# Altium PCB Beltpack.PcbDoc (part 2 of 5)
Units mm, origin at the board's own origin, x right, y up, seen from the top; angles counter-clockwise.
Board outline 85 x 81 mm, 4 copper layers (Top Layer, Inner-1, Inner_GND, Bottom Layer), stack 1.556 mm thick; 389 components, 291 nets, 1372 pads, 660 vias.
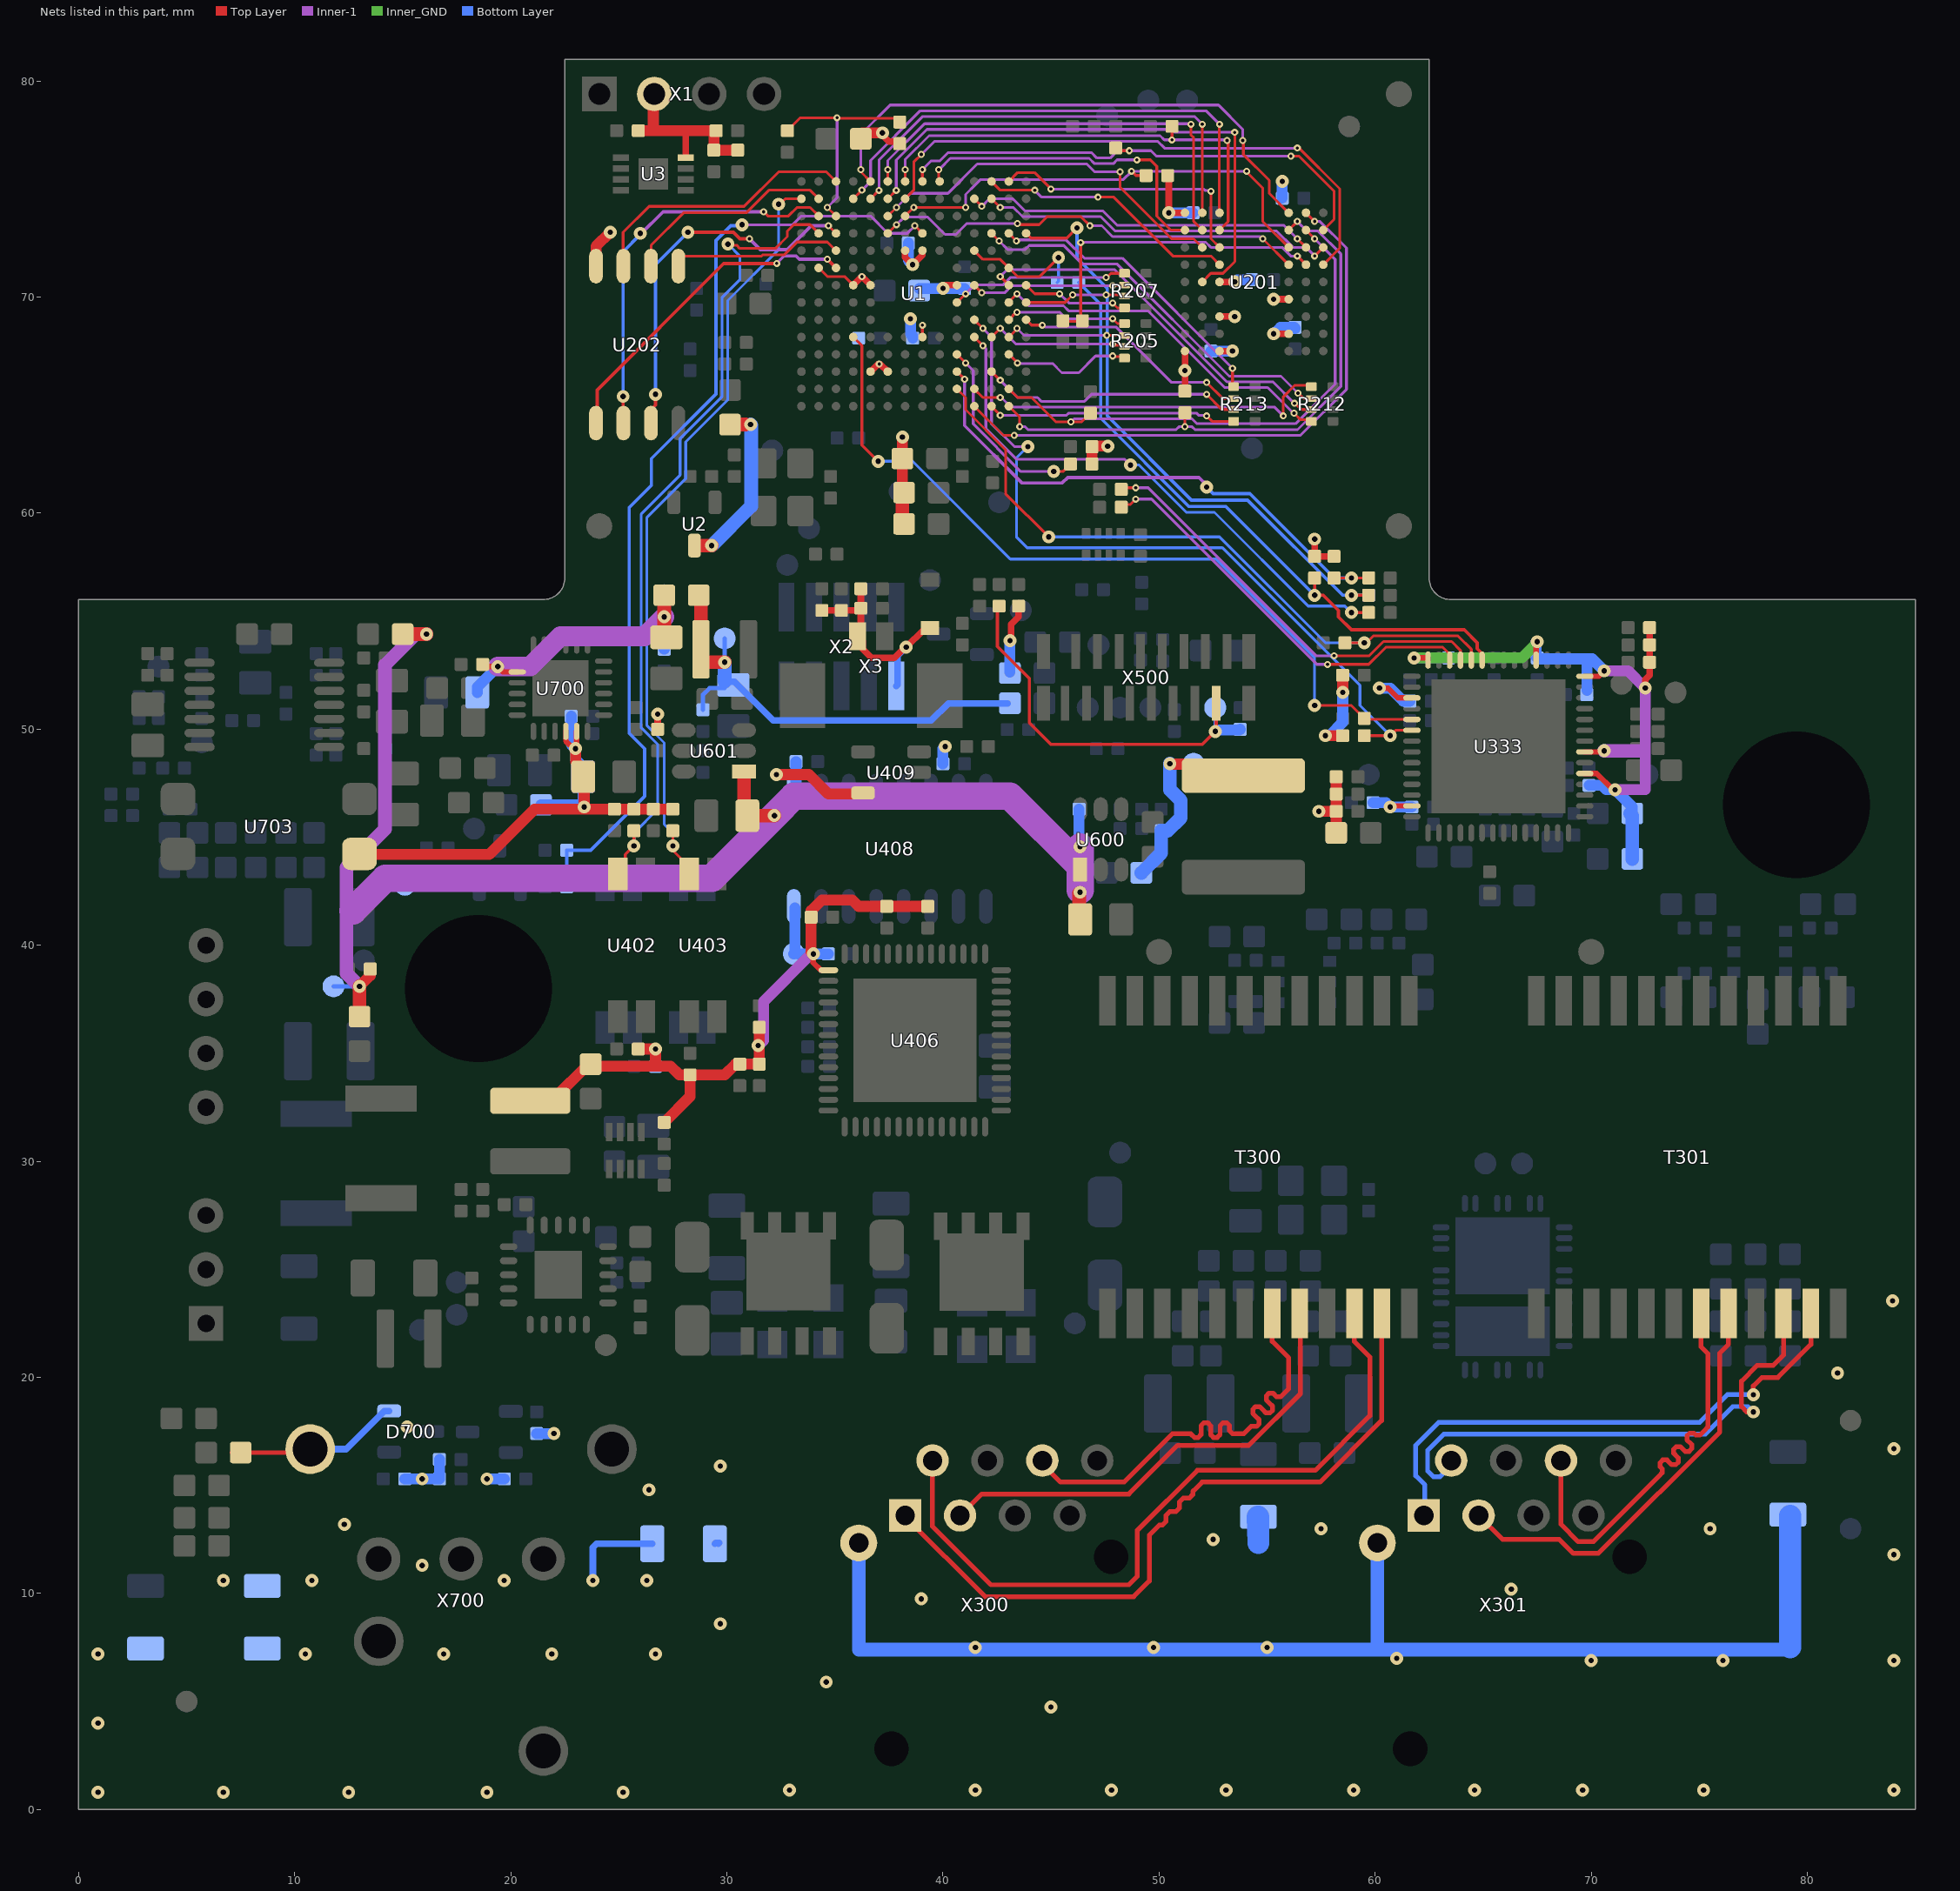
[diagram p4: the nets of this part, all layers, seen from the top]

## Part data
C1 C2: library part C.C0G0402TJ-15P0, "Capacitor C0G, 0402, 50V, 5%", Mfr Name=Murata, Mfr Part No=GRM1555C1H150JA01D
C3 C5 C19 C310 C713: library part C.C0G0402TJ-220P, "Capacitor C0G, 0402, 50V, 5%", Mfr Name=Murata, Mfr Part No=GRM1555C1H221JA01D, VOLTAGE=50V
C4 C7 C9 C10 C12 C15 C200 C201 C202 C203 C204 C205 C300 C301 C302 C303 C304 C305 C306 C308 C309 C313 C315 C316 C318 C412 C416 C417 C418 C605 C700 C702 C704 C706 C708 C711 C723 C725: library part C.X7R0402CM-100N, "Capacitor X7R, 0402, 16V, 20%", Mfr Name=Kemet, Mfr Part No=C0402C104M4RACAUTO, VOLTAGE=16V
C6 C8 C13: library part C.X7R0603TK-4N70, "Capacitor X7R, 0603, 50V, 10%", Mfr Name=Panasonic, Mfr Part No=ECJ1VB1H472K
C11 C16 C307 C311 C312 C317 C410 C600 C603 C710 C714 C715 C722: library part C.X7R0603EK-1U00, "Capacitor X7R, 0603, 25V, 10%", Mfr Name=Murata, Mfr Part No=GRM188R71E105KA12D, VOLTAGE=25V
C14 C411 C602: library part C.X5R0603JM-22U0, "Capacitor X5R, 0603, 6V3, 20%", Mfr Name="TDK Corporation", Mfr Part No=GRM188R60J226MEA0J, VOLTAGE=6.3V
C17 C18: library part C.X7R0603EK-1U00, "Capacitor X7R, 0603, 25V, 10%", Mfr Name=Samsung, Mfr Part No=CL10B105KA8NFNC, VOLTAGE=25V
C20 C21 C22 C23 C24: library part C.C0G0402TJ-47P0, "Capacitor C0G, 0402, 50V, 5%", Mfr Name=Murata, Mfr Part No=GJM1555C1H470JB01D, VOLTAGE=50V
C206 C319 C320 C323 C328 C333 C334 C335 C336: library part C.C0G0402TJ-10P0, "Capacitor C0G, 0402, 50V, 5%", Mfr Name=Murata, Mfr Part No=GRM1555C1H100JZ01D, VOLTAGE=50V
C314 C331 C337 C338 C709: library part C.X7R1206WK-1N00, "Capacitor X7R, 1206, 2000V, 10%", Mfr Name=AVX, Mfr Part No=1206GC102KAT1AJ, VOLTAGE=2000V
C321 C322 C324 C325 C326 C327 C329 C402 C405: library part C.X7R0603BK-10N0, "Capacitor X7R, 0603, 100V, 10%", Mfr Name=Samsung, Mfr Part No=CL10B103KC85PNC, VOLTAGE=100V
C330 C332: library part C.X7R0603TK-22N0, "Capacitor X7R, 0603, 50V, 10%", Mfr Name=Panasonic, Mfr Part No=ECJ1VB1H223K, VOLTAGE=50V
C400 C406: library part C.X7R1808HK-1N50, "Capacitor X7R, 1808, 3000V, 10%", Mfr Name=Yageo, Mfr Part No=CC1808KKX7REBB152, VOLTAGE=3kV
C401 C407: library part C.X7R1206BK-2U20, "Capacitor X7R, 1206, 100V, 10%", Mfr Name=Murata, Mfr Part No=GRM31CR72A225KA73L, VOLTAGE=100V
C403: library part C.C0G0402BK-1N00, "Capacitor X7R, 0402, 100V, 10%", Mfr Name=Murata, Mfr Part No=GCM155R72A102KA37D, VOLTAGE=100V
C404 C413 C414 C415: library part C.X7R0805BK-100N, "Capacitor X7R, 0805, 100V, 10%", Mfr Name=Samsung, Mfr Part No=CL21B104KCFWPNE, VOLTAGE=100V
C408 C419: library part C.X6S1210CK-47U0, "Capacitor X6S, 1210, 16V, 10%", Mfr Name=Murata, Mfr Part No=GRM32EC81C476KE15K, VOLTAGE=16V
C409: library part C.X7S0805BK-1U00, "Capacitor X7R, 0805, 100V, 10%", Mfr Name=Murata, Mfr Part No=GRJ21BC72A105KE11L, VOLTAGE=100V
C601 C604 C607 C724: library part C.X5R0805CK-22U0, "Capacitor X5R, 0805, 16V, 10%", Mfr Name="TDK Corporation", Mfr Part No=C2012X5R1C226K125AC, VOLTAGE=16V
C606 C701 C703 C705 C707 C712 C716 C726: library part C.X5R0805AK-4U70, "Capacitor X5R, 0805, 10V, 10%", Mfr Name=Murata, Mfr Part No=GRM21BR61A475KA12L, VOLTAGE=10V
C717: library part C.X5R0805CK-2U20, "Capacitor X5R, 0805, 16V, 10%", Mfr Name=Kemet, Mfr Part No=C0805C225K4PACTU, VOLTAGE=16V
C718 C719 C720 C721 C728: library part C.C0G0402TJ-47P0, "Capacitor C0G, 0402, 50V, 5%", Mfr Name=Murata, Mfr Part No=GRM1555C1H470JA01D, VOLTAGE=50V
D1: library part D.1N4148WS, "Diode, 350mA, 100V, SOD-323", Mfr Name=Vishay, Mfr Part No=1N4148WS-E3-08
D300 D301: library part D.TVS3V3L4U, "TVS Diode Array, 3.3V, 2pF, SC74-6", Mfr Name=Infineon, Mfr Part No=TVS3V3L4UE6327HTSA1
D400: library part D.PD70224ILQ, "Bridge Rectifier Dual MOSFET, 57V, PoE, SMD", Mfr Name="Microsemi Corp.", Mfr Part No=PD70224ILQ-TR
D401 D402 D403: library part D.SMAJ58A, "Diode, Transient voltage suppressor, 58V, 400W, SMA", Mfr Name="Diodes Inc", Mfr Part No=SMAJ58A-13-F
D404 D405: library part D.TVS-VC121060J121DP, "Diode, TVS, bidirectional, Vw=60V, Vb=76V, 250W, 1210", Mfr Name="AVX Corporation"
D700 D701: library part D.PESD24VL2BT, "Diode, dual ESD, 24Vrwm, 11pF, SOT-23", Mfr Name="NXP Semiconductors", Mfr Part No=PESD24VL2BT,215
F400 F401: library part F.C1S-1.5, "Fuse, 1.25A, 63V, 1206", Mfr Name="Bel Fuse Inc.", Mfr Part No="C1S 1.5"
L1 L2 L3 L300 L301 L302 L303 L404 L601 L700 L701 L702 L703 L704 L705: library part L.FB_0603_330R_1A5, "Inductor SMD, >1.5A, 330Ohm@100MHz, 0603", Mfr Name="TDK Corporation", Mfr Part No=MPZ1608S331ATA00
L400: library part L.NR3015-10U0, "Inductor, SMD, 0.7A, 0.28 Ohm, 20%, shielded", Mfr Name="Taiyo Yuden", Mfr Part No=NR3015T100M
L401 L402: library part L.MPZ2012S601AT000, "Inductor SMD, 2.0 A, 600 Ohm@100MHz, 0805", Current Rating=2A, Mfr Name="TDK Corporation", Mfr Part No=MPZ2012S601AT000
L403: library part L.NR4018T-33U0, "Inductor, SMD, 550mA, 0.552 Ohm, 20%", Mfr Name="Taiyo Yuden", Mfr Part No=NRS4018T330MDGJV
L600: library part L.NRS6028T-22U0, "Inductor, SMD, 1.3A, 0.14 Ohm, 20%, shielded", Mfr Name="Taiyo Yuden", Mfr Part No=NRS6028T220MMGJ
L602: library part L.NR3015-22U0, "Inductor, SMD, 0.47A, 0.62 Ohm, 20%, shielded", Mfr Name="Taiyo Yuden", Mfr Part No=NR3015T220M
Q1: library part Q.ABM8G-12.000M, "Quartz SMD, 3.2x2.5mm, -10...+70°C, ±30 ppm, 10pF", Mfr Part No=ABM8G-12.000MHZ-B4Y-T
R1 R15 R16 R400 R404 R413 R415: library part R.CH0402GF-4K70, "Resistor, Chip 0402, 0.063W, 1%, 100ppm", Mfr Name=Panasonic, Mfr Part No=ERJ-2RKF4701X
R2 R300: library part R.CH0402GF-12K1, "Resistor, Chip 0402, 0.063W, 1%, 100ppm", Mfr Name=Yageo, Mfr Part No=RC0402FR-0712K1L
R3 R4 R5 R6 R7 R8 R9 R11 R13 R202 R203 R204 R206 R208 R209 R210 R211 R218 R320 R321 R322 R323 R324 R325 R326 R327 R328 R329 R330 R331 R332 R333 R335 R337 R338 R418 R431 R432 R703 R720 R721 R722 R723: library part R.CH0402GF-10K0, "Resistor, Chip 0402, 0.063W, 1%, 100ppm", Mfr Name=Rohm, Mfr Part No="MCR01 MZP F 1002"
R10 R26 R334 R410 R411 R419 R420 R421 R422 R427 R428 R429 R430: library part R.CH0402GF-1K00, "Resistor, Chip 0402, 0.063W, 1%, 100ppm", Mfr Name=Yageo, Mfr Part No=RC0402FR-071KL
R12 R205 R207 R212 R213: library part R.CH4X0402JH-33R0, "Chip Resistor Array 4 X 0402 5% 200ppm", Mfr Name=Panasonic, Mfr Part No=EXB-N8V330JX
R14 R17 R20 R200 R201 R214 R302 R303 R304 R336: library part R.CH0402GF-33R0, "Resistor, Chip 0402, 0.063W, 1%, 100ppm"
R18 R215 R216 R217 R702: library part R.CH0402GF-47R0, "Resistor, Chip 0402, 0.063W, 1%, 100ppm", Mfr Name=Yageo, Mfr Part No=RC0402FR-0747RL
R19: library part R.CH0402GF-47R0, "Resistor, Chip 0402, 0.063W, 1%, 100ppm", Mfr Name=Rohm, Mfr Part No="MCR03 EZP FX 4700"
R305 R306 R307 R308 R313 R314 R315 R319: library part R.CH0603GF-49R9, "Resistor, Chip 0603, 1%, 100ppm", Mfr Name=Samsung, Mfr Part No=RC1608F49R9CS
R309 R310 R311 R312 R316 R317 R318: library part R.CH0603GF-75R0, "Resistor, Chip 0603, 1%, 100ppm", Mfr Name=Rohm, Mfr Part No="MCR03 EZP FX 75R0"
R401: library part R.CH0402GF-24K9, "Resistor, Chip 0402, 0.063W, 1%, 100ppm", Mfr Name=Yageo, Mfr Part No=RC0402FR-0724K9L
R402 R601 R602 R604 R606 R705 R707 R728: library part R.CH0402GF-47K0, "Resistor, Chip 0402, 0.063W, 1%, 100ppm", Mfr Name=Rohm, Mfr Part No="MCR01 MZP F 4702"
R403: library part R.CH0402GF-1K30, "Resistor, Chip 0402, 0.063W, 1%, 100ppm", Mfr Name=Yageo, Mfr Part No=RC0402FR-071K3L
R405: library part R.CH0603GF-63R4, "Resistor, Chip 0603, 1%, 100ppm", Mfr Name=Yageo, Mfr Part No=RC0603FR-0763R4L
R406: library part R.CH0603GF-90R9, "Resistor, Chip 0603, 1%, 100ppm", Mfr Name=Yageo, Mfr Part No=RC0603FR-0790R9L
R407: library part R.CH0402XX-0R00, "Resistor, Chip 0402", Mfr Name=Rohm, Mfr Part No=MCR01MZPJ000
R408: library part R.CH0402GF-49K9, "Resistor, Chip 0402, 0.063W, 1%, 100ppm", Mfr Name=Yageo, Mfr Part No=RC0402FR-0749K9L
R409: library part R.CH0603GF-62K0, "Resistor, Chip 0603, 1%, 100ppm", Mfr Name=Samsung, Mfr Part No=RC1608F623CS
R412: library part R.CH0402GF-120K, "Resistor, Chip 0402, 0.063W, 1%, 100ppm", Mfr Name=Yageo, Mfr Part No=RC0402FR-07120KL
R414: library part R.CH0402GF-150K, "Resistor, Chip 0402, 0.063W, 1%, 100ppm", Mfr Name=Samsung, Mfr Part No=RC1005F154CS
R416: library part R.CH0402GF-5K60, "Resistor, Chip 0402, 0.063W, 1%, 100ppm", Mfr Name=Panasonic, Mfr Part No=ERJ-2RKF5601X
R417: library part R.CH0402GF-56K0, "Resistor, Chip 0402, 0.063W, 1%, 100ppm", Mfr Name=Yageo, Mfr Part No=RC0402FR-0756KL
R423 R424 R425 R426: library part R.CH0805GF-0R51, "Resistor, Chip 0805, 1%, 100ppm", Mfr Name=Bourns, Mfr Part No=CRM0805-FX-R510ELF
R600: library part R.CH0402GF-100K, "Resistor, Chip 0402, 0.063W, 1%, 100ppm", Mfr Name=Rohm, Mfr Part No=MCR01MRTF1003
R603 R711: library part R.CH0402GF-15K0, "Resistor, Chip 0402, 0.063W, 1%, 100ppm", Mfr Name=Rohm, Mfr Part No="MCR01 MZP F 1502"
R605 R714 R715: library part R.CH0402GF-36K0, "Resistor, Chip 0402, 0.063W, 1%, 100ppm", Mfr Name=Yageo, Mfr Part No=RC0402FR-0736KL
R607: library part R.CH0402GF-6K80, "Resistor, Chip 0402, 0.063W, 1%, 100ppm", Mfr Name=Rohm, Mfr Part No=MCR01MRTF6801
R700 R704 R724: library part R.CH0402GF-10k0, "Resistor, Chip 0402, 0.063W, 1%, 100ppm", Mfr Name=Rohm, Mfr Part No="MCR01 MZP F 1002"
R701 R719: library part R.CH0402GF-270R, "Resistor, Chip 0402, 0.063W, 1%, 100ppm", Mfr Name=Yageo, Mfr Part No=RC0402FR-07270RL
R706: library part R.CH0402GF-2K20, "Resistor, Chip 0402, 0.063W, 1%, 100ppm", Mfr Name=Vishay, Mfr Part No=CRCW04022K20FKED
R708 R710 R713 R716 R717 R718: library part R.CH0603GF-39R0, "Resistor, Chip 0603, 1%, 100ppm"
R709: library part R.CH0402GF-47K0, "Resistor, Chip 0402, 0.063W, 1%, 100ppm", Mfr Name=Yageo, Mfr Part No=RC0402FR-0747KL
R712: library part R.CH0603XX-0R00, "Resistor, Chip 0603", Mfr Name=Yageo, Mfr Part No=RC0603JR-070RL
T300 T301: library part T.ETH_1000BASET_4PPOE, "Transformer, Ethernet 1000BASE-T, 1:1, 4PPoE, SMD", Mfr Name="Würth Elektronik GmbH", Mfr Part No=7490220122
TP1 TP2 TP3 TP4 TP5 TP6 TP7 TP8 TP9 TP10 TP11 TP12 TP13 TP14 TP100 TP200 TP300 TP301 TP302 TP303 TP400 TP401 TP402 TP403 TP404 TP405 TP406 TP407 TP408 TP409 TP410 TP600 TP601 TP602 TP700 TP701 TP702 TP703 X4 X5 X6 X7 X8: library part Testpoint, "Testpoint"
U1: library part U.LPC43S50FET180, "IC, MCU, 32bit, 264kB secure, SRAM, USB-PHY, Ethernet, CAN, AES, OTP-secured, TFBGA-180", Manufacturer="NXP Semiconductors", Mfr Part No=LPC43S50FET180E
U2: library part U.TPS3809K33DBV, "IC, Voltage Supervisor, 2.93V, SOT23", Mfr Name="Texas Instruments"
U3: library part U.ATSHA204A-MAHDA-T, "IC, Crypto-Authentication, 2.0-5.5V, 4.5kB EEPROM, 512bit OTP, programmed, I2C, UDFN-8", Mfr Name="Atmel Corperation", Mfr Part No=ATSHA204A-MAHDA-T
U201: library part U.SDRAM_4MX16_166M_BGA54, "IC, SDRAM, 64Mbit, 166MHz, 3.3V, 0..+70°C, BGA54", Mfr Name="Intelligent Memory", Mfr Part No=IM6416SDBABG-6
U202: library part U.FL_NOR_QSPI_8MX8_SO8W, "IC, QSPI FLASH, 64Mbit, 3.3V, SO-8 (wide)", Mfr Name=Cypress
U333: library part U.LAN9354, "IC, 3Port 10/100 Switch with 2PHYs, QFN-56", Mfr Name=Microchip, Mfr Part No=LAN9354/ML
U400: library part U.TPS2372-4RGW, "IC, PoE PD Interface, 802.3bt, 90W, VQFN-20", Mfr Name="Texas Instruments", Mfr Part No=TPS2372-4RGW
U401: library part U.SPBW06G-12, "Converter DC-DC, isolated, 18..75V input, 12V/0.5A output, SIP8", Mfr Name="Mean Well Inc."
U402 U403 U405 U407: library part U.EL3H7(TA), "IC, Optocoupler, Vce 80V, 3.75kV(rms)", Mfr Name=Everlight, Mfr Part No=EL3H7(TA)-VG
U404: library part U.MAX15062C, "IC, PWM Converter, buck, adjustable, 60V, 300mA, TDFN8", Mfr Name=Maxim, Mfr Part No=MAX15062CATA+T
U406: library part U.TPS23880RTQ, "IC, PoE PSE Controller, 802.3bt, VQFN-56"
U408: library part U.SI8631AB-B-IS1, "IC, Digital Isolator, 2.5kV, 1Mbps, 2/1, SO16 (narrow)", Mfr Name="Silicon Laboratories Inc.", Mfr Part No=SI8631AB-B-IS1
U409: library part U.74LVC1G07DBV, "IC, Single buffer with open-collector, SOT23-5", Mfr Name="Texas Instruments", Mfr Part No=SN74LVC1G07DBVRG4
U600 U601: library part U.AP65111A, "IC, PWM converter, buck, 4.5...18V, 1.5A, 500kHz, TSOT26", Mfr Name="Diodes Inc", Mfr Part No=AP65111AWU-7
U700: library part U.WM8974CGEFL, "IC, Codec, mono, 98dB, 48 kHz, -40 to +85°C, QFN-24", Mfr Name="Cirrus Logic", Mfr Part No=WM8974CGEFL/V
U701: library part U.TS9224IPT, "IC, Quad OpAmp, 80mA out, RR I/O, 9nV, TSSOP14", Mfr Name=STMicroelectronics
U703: library part U.G3VM-41DY1, "IC, Solid State Relays, 40V, 2A, SMD", Mfr Name=Omron, Mfr Part No=G3VM-41DY1
V1 V700: library part V.BC846B, "Transistor NPN, 65V, 0.1A, SOT23", Mfr Name="Fairchild Semiconductor", Mfr Part No=BC846BMTF
V402 V403: library part V.SQJ476EP, "Transistor MOSFET N-Channel, 100V, 23A, SO8L", Mfr Name=Vishay, Mfr Part No=SQJ476EP-T1_GE3
X1: library part J.1X4_2M54, "Pin Header 1x4pin, 2.54mm pitch, gold/tin, 5.84/3.05mm"
X2: library part J.2X5_1M27_F_SMD, "Receptacle 2x5pin, 1.27mm pitch, 3mm pins, straight, SMD", Mfr Name=FCI, Mfr Part No=20021121-00010C4LF
X3: library part X.MOLEX-53398-HEADER-2P, "Header 2pin, shrouded, 1.25mm pitch, straight, male blade, shrouded", Mfr Name=Molex
X300 X301: library part X.RJ45-NE8FAH, "Connector RJ-45 Jack, 8 Pins, Right-Angle, Push lock", Mfr Name=Neutrik
X500: library part X.FFC-16P-0.5MM-62674, "Connector FPC/FFC, 16pin, 0.5mm pitch, vertical, single-side, ZIF, SMD", Mfr Name=Amphenol
X700: library part X.XLR-NC4MAH, "Connector XLR Jack, 4 Pins, Right-Angle", Mfr Name=Neutrik

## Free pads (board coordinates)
  round 3 hole 6.8 unplated: HOLE1(18.5,38) HOLE2(79.5,46.5)

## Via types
v1: diameter 0.6, hole 0.25, Top Layer to Bottom Layer, 460 vias
v2: diameter 0.325, hole 0.15, Top Layer to Inner-1, 145 vias
v3: diameter 0.55, hole 0.2, Top Layer to Bottom Layer, 41 vias
v4: diameter 0.325, hole 0.15, Top Layer to Inner-1, tented both sides, 8 vias
v5: diameter 1.6, hole 1.016, Top Layer to Bottom Layer, 5 vias
v6: diameter 0.6, hole 0.25, Top Layer to Bottom Layer, tented both sides, 1 vias

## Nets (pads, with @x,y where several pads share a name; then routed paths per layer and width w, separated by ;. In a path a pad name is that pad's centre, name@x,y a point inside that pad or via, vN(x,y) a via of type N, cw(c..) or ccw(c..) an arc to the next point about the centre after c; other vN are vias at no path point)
3V3: C4.1 C6.1 C7.1 C8.1 C9.1 C10.1 C11.1 C12.1 C13.1 C14.1 C200.1 C201.1 C202.1 C203.1 C204.1 C205.1 C301.1 C302.1 C303.1 C304.1 C305.1 C306.1 C417.2 C602.1 C702.2 C703.2 C706.2 C707.2 D1.C L1.2 L3.2 L300.1 L302.1 L303.1 L600.2 L700.2 R1.1 R4.2 R5.2 R6.2 R7.2 R8.2 R13.1 R15.1 R16.1 R202.2 R203.2 R211.2 R323.1 R324.1 R326.1 R327.2 R328.2 R329.2 R330.2 R332.1 R333.1 R334.2 R335.2 R418.1 R420.2 R422.2 R431.1 R432.1 R601.1 R604.2 TP600.1 U1.B9 U1.D8 U1.E3 U1.E8 U1.F3 U1.G10 U1.H5 U1.H10 U1.K8 U2.3 U3.8 U201.A7 U201.A9 U201.B3 U201.C7 U201.D3 U201.E7 U201.J9 U202.8 U333.5 U333.7 U333.14 U333.18 U333.28 U333.31 U333.41 U408.1 U409.5 U700.4 U700.5 U703.1 X1.2 X2.1 X3.1 | length 160.3
  Top Layer w0.127: U1.B9@34.25,71.35 34.65,70.95 35.45,70.95 U1.D8@35.85,70.55 ; U1.H5@39.05,68.15 v2@39.05,68.6
  Top Layer w0.254: U700.4@22.55,49.9 22.55,49.45 22.95,49.05 v1(23,49.1) ; v1@23.05,49.15 U700.5@23.05,49.9 ; v1(60.2,51.9) 60.6,51.9 61.048,51.452 61.698,51.452 U333.31@61.7,51.45 ; v1@60.7,46.45 U333.41@61.7,46.45 ; v1(61.8,53.3) 62.45,53.3 U333.28@62.45,53.2 ; U333.18@67.45,53.2 v1@67.45,54.05 ; U333.5@69.7,47.95 70.25,47.95 71,47.2 v1(71.1,47.2) ; U333.7@69.7,48.95 v1@70.45,48.95 ; U333.14@69.7,52.45 70.35,52.45 v1(70.6,52.7)
  Top Layer w0.305: R604.2@26.8,50 v1(26.8,50.7) ; U3.8@28.1,76.5 28.1,77.7 ; R5.2@34.4,55.4 R5.2@34.5,55.5 ; R5.2@34.4,55.5 R5.2@34.5,55.5 ; R6.2@35.3,55.4 35.2,55.5 R5.2@34.5,55.5 ; R6.2@35.3,55.5 36.1,55.5 36.2,55.4 36.2,54.45 X3.1@36.05,54.3 36.298,54.052 36.298,53.702 36.7,53.3 37.756,53.3 38.156,53.7 v1@38.2,53.7 ; U1.D8@35.85,70.55 v2(36.25,70.95) U1.E8@36.65,70.55 ; C4.1@36.2,55.6 R7.2@36.2,56.5 ; U1.E3@36.65,66.55 37,66.9 v2(37.05,66.9) 37.1,66.9 U1.F3@37.45,66.55 ; v1(37.2,77.6) 37.2,77.5 37.5,77.2 37.9,77.2 R211.2@38,77.1 ; v1(38.3,53.8) 39.1,54.6 39.315,54.6 D1.C@39.4,54.685 ; U1.G10@38.3,72.15 U1.G10@38.25,72.15 38.25,71.85 38.55,71.55 v1@38.6,71.6 ; v1(38.6,71.5) 39.05,71.95 U1.H10@39.05,72.15 ; v1(40,70.4) 40.15,70.55 U1.K8@40.65,70.55 ; v1(43.1,54.1) 43.156,54.156 43.156,54.856 43.5,55.2 R1.1@43.5,55.7 ; R203.2@50.4,75.625 50.45,75.575 50.45,73.95 50.5,73.9 U201.J9@51.2,73.9 ; R202.2@51.2,65.65 v1(51.2,66.6) U201.A9@51.2,67.5 ; U201.A7@52.8,67.5 v1(53.4,67.5) ; U201.C7@52.8,69.1 v1(53.5,69.1) ; U201.E7@52.8,70.7 v1(53.5,70.7) ; v1(55.3,68.3) U201.B3@56,68.3 ; v1(55.3,69.9) U201.D3@56,69.9 ; v1@57.2,58.7 R327.2@57.2,58 R328.2@58.1,58 ; v1(72.5,51.9) 72.5,52.3 72.7,52.5 R326.1@72.7,53.1 R330.2@72.7,54.7
  Top Layer w0.508: U703.1@13,44.2 19,44.2 21.1,46.3 v1@23.4,46.3 ; v1(23,49.1) 23,48.5 23.35,48.15 C703.2@23.35,47.8 ; C703.2@23.4,47.8 v1(23.4,46.4) v1@23.4,46.3 ; U202.8@23.95,71.432 23.95,72.35 v1(24.6,73) ; C205.1@25.9,77.7 26.5,77.7 26.6,77.7 ; X1.2@26.64,79.4 26.6,79.36 26.6,77.7 ; R432.1@27.5,46.3 R420.2@26.6,46.3 R431.1@25.7,46.3 R418.1@24.8,46.3 v1@23.4,46.3 ; R16.1@30.5,76.8 R15.1@29.4,76.8 29.4,77.7 26.6,77.7 ; v1@30.875,64.1 v1(31.1,64.1) ; v1(32.3,47.9) 33.8,47.9 34.7,47 U409.5@36.3,47 ; C8.1@36.15,77.5 C8.1@36.187,77.538 ; C8.1@36.2,77.525 36.275,77.6 v1(37.2,77.6) ; U409.5@36.25,47.05 U409.5@36.3,47.1 ; C11.1@38.05,60.95 38.125,61.025 C6.1@38.125,62.525 v1(38.125,63.525) ; R4.2@46.9,62.275 46.9,63.025 46.975,63.1 v1(47.625,63.1) ; v1(50.5,48.4) 50.518,48.382 53.368,48.382 L600.2@53.9,47.85 ; v1(57.4,46.2) R323.1@58.2,46.2 ; v1@57.8,49.7 R334.2@58.5,49.7 ; L303.1@58.2,45.2 L303.1@58.4,45.4 ; L303.1@58.2,45.4 R323.1@58.2,46.2 ; R324.1@58.2,47.7 R332.1@58.2,47 R323.1@58.2,46.2 ; v1(58.5,51.7) R329.2@58.5,52.5
  Top Layer w0.635: U2.3@28.6,58.5 v1(29.3,58.5) ; L1.2@30.1,64.1 v1@30.875,64.1 ; C11.1@38.05,60.95 38.125,60.875 C14.1@38.125,59.5
  Inner-1 w0.508: v1(70.6,52.7) 71.7,52.7 v1(72.5,51.9) 72.5,47.2 v1(71.1,47.2)
  Inner-1 w0.635: v1(70.6,49) 72.4,49
  Inner_GND w0.508: v1(61.8,53.3) 66.8,53.3 v1@67.5,54
  Bottom Layer w0.152: v1(50.5,48.4) TP600.1@51.6,48.4
  Bottom Layer w0.254: C303.1@67.45,53.35 C303.1@67.5,53.3
  Bottom Layer w0.305: X2.1@37.84,52 37.9,52.06 37.9,53.4 v1@38.2,53.7
  Bottom Layer w0.508: L700.2@21.4,46.5 23.35,46.5 C707.2@23.35,47.8 23.35,48.25 23,48.6 v1(23,49.1) 22.8,49.3 C706.2@22.8,49.8 C702.2@22.8,50.6 ; v1(32.3,47.9) U408.1@33.2,47.9 ; U408.1@33.1,46.867 U408.1@33.1,47.134 ; U408.1@33.155,47.067 U408.1@33.194,47.106 ; U408.1@33.2,47.1 U408.1@33.2,47.9 ; C417.2@33.2,48.5 U408.1@33.2,47.9 ; C12.1@38.4,72.5 38.4,71.7 v1@38.5,71.6 ; v1(38.5,69) 38.5,68.3 38.6,68.2 C7.1@38.6,68.1 ; C13.1@38.9,70.4 v1(40,70.4) C9.1@41,70.4 ; R422.2@40,48.4 40,49.1 v1(40.1,49.2) ; L3.2@43.1,52.65 v1(43.1,54.1) ; v1(50.45,73.9) C200.1@51.575,73.9 ; C204.1@52.4,67.5 v1(53.4,67.5) ; v1(53.5,70.7) 53.525,70.7 53.625,70.8 C202.1@54.3,70.8 ; v1(55.3,68.3) 55.325,68.3 55.625,68.6 56.254,68.6 C203.1@56.3,68.554 ; C201.1@55.7,74.575 v1(55.7,75.35) ; v1(57.7,49.7) 57.718,49.718 57.892,49.718 58.5,50.326 v1(58.5,51.7) ; R335.2@59.9,46.6 60.5,46.6 v1(60.7,46.4) C306.1@61.7,46.4 ; v1(60.2,51.9) 60.7,51.9 61.3,51.3 C305.1@61.6,51.3 ; v1(61.8,53.3) C304.1@63.4,53.3 ; C303.1@67.45,53.35 v1@67.45,54.05 ; C303.1@67.5,53.3 67.546,53.254 70.046,53.254 v1(70.6,52.7) ; C302.1@69.8,51.8 69.8,52.3 69.8,53.2 ; C301.1@69.9,47.4 70.5,47.4 70.7,47.2 v1(71.1,47.2) 71.9,46.4 L302.1@71.9,46.1
  Bottom Layer w0.635: v1(29.3,58.5) 31.122,60.322 31.122,64.078 v1(31.1,64.1) ; C602.1@49.18,43.351 50.1,44.271 R601.1@50.1,45.3 50.4,45.3 51,45.9 51,46.7 50.5,47.2 v1(50.5,48.4) ; L302.1@71.8,46.1 71.9,46 L300.1@71.9,44
  other v1: 67.5,54.05 57.2,58.8
  other v2: 39.05,68.7
3V3PSE: C411.1 C412.2 C416.2 L403.2 R400.1 R404.1 R410.1 R411.1 R413.1 R414.1 R415.1 R419.1 R421.2 TP406.1 U406.43 U408.16 | length 36.6
  Top Layer w0.254: v1(34,39.6) 34,39.2 34.35,38.85 U406.43@34.7,38.85 34.697,38.853 U406.43@34.347,38.853
  Top Layer w0.508: L403.2@20.8,32.9 L403.2@22.3,32.9 ; L403.2@22.1,33 C411.1@23.5,34.4 ; C411.1@23.7,34.5 23.8,34.4 26.7,34.4 ; R410.1@25.9,35.2 v1(26.7,35.2) 26.7,34.4 ; R414.1@27.1,31.8 28.3,33 R411.1@28.3,34 ; R415.1@31.5,34.5 R413.1@30.6,34.5 30.4,34.5 29.9,34 R411.1@28.3,34 ; R415.1@31.5,34.6 R400.1@31.5,36.2 ; C416.2@33.9,41.3 C416.2@33.9,41.5 ; v1(34,39.6) 33.9,39.7 C416.2@33.9,41.5 ; R404.1@37.2,41.8 36.1,41.8 35.8,42.1 34.4,42.1 33.9,41.6 C416.2@33.9,41.5 ; R404.1@37.4,41.8 R421.2@39.3,41.8 ; 26.7,34.4 27.4,34.4 27.8,34 R411.1@28.3,34
  Inner-1 w0.508: v1@31.5,35.4 31.7,35.6 31.7,37.4 33.9,39.6 v1(34,39.6)
  Bottom Layer w0.508: R419.1@26.7,34.4 v1(26.7,35.2) ; TP406.1@33.1,39.6 33.155,39.655 U408.16@33.155,41.733 ; TP406.1@33.3,39.6 v1(34,39.6) C412.2@34.7,39.6
  other v1: 31.448,35.357
5VA: C605.2 C606.2 C700.2 C701.2 L601.1 TP602.1 U700.20 | length 16.5
  Top Layer w0.254: C700.2@18.7,52.9 v1(19.4,52.9) 19.65,52.65 U700.20@20.3,52.65
  Top Layer w0.635: C606.2@27.1,54.1 L601.1@27.1,56.2
  Inner-1 w0.914: v1(19.4,52.9) 20.9,52.9 22.3,54.3 26.2,54.3 v1(27.1,55.2)
  Bottom Layer w0.203: v1(27.1,55.2) TP602.1@27.1,56.2
  Bottom Layer w0.508: C701.2@18.45,51.7 18.45,51.95 v1(19.4,52.9) ; C605.2@27.1,53.7 v1(27.1,55.2)
5VD: C607.1 L2.2 L601.2 L602.2 R605.1 TP601.1 | length 21.8
  Top Layer w0.635: L601.2@28.8,56.1 L602.2@28.8,53.7 28.8,53.1 v1(29.9,53.1)
  Bottom Layer w0.203: R605.1@28.9,50.9 28.9,51.6 29.2,51.9 C607.1@29.9,51.9 ; v1(29.9,53.1) TP601.1@29.9,54.2
  Bottom Layer w0.305: C607.1@30.2,52.2 30.35,52.2 32.15,50.4 39.45,50.4 40.25,51.2 L2.2@43,51.2
  Bottom Layer w0.635: C607.1@29.9,52.2 v1(29.9,53.1)
+12V: C418.1 C601.1 C604.1 L404.1 L703.1 R600.1 TP402.1 U600.1 U601.1 | length 68.3
  Top Layer w0.508: v1(13,38.1) 13.5,38.6 C418.1@13.5,38.9 ; C601.1@46.2,41.4 C601.1@46.4,41.2
  Top Layer w0.635: L404.1@12.9,36.7 13,36.8 v1(13,38.1) ; L703.1@15,54.4 v1(16.1,54.4) ; U601.1@30.797,48.047 30.797,46.003 C604.1@30.8,46 ; C604.1@30.95,46 v1(32.2,46) ; v1@46.3,42.4 46.3,41.75 C601.1@46.325,41.725
  Inner-1 w0.635: v1(13,38.1) 12.4,38.7 12.4,43.6 14.175,45.375 14.175,52.975 15.6,54.4 v1(16.1,54.4)
  Inner-1 w1.27: 12.7,41.6 14.2,43.1 29.3,43.1 v1(32.2,46) 33.1,46.9 43.1,46.9 46.348,43.652 ; v1@46.348,42.552 46.348,43.652 ; v1(46.348,44.557) 46.348,43.652
  Bottom Layer w0.203: TP402.1@11.8,38.1 v1(13,38.1)
  Bottom Layer w0.508: R600.1@46.3,46.3 46.3,44.605 v1(46.348,44.557)
  other v1: 46.348,42.457
A0: R208.1 U1.G14 U201.H7 | length 21.4
  Top Layer w0.127: U1.G14@38.25,75.35 v2(38.25,75.9) ; v2(50.6,77.275) R208.1@50.6,77.9 ; U201.H7@52.8,73.1 53.199,73.499 53.199,77.202 v2(53.15,77.25)
  Inner-1 w0.127: v2(38.25,75.9) 38.25,76.361 39.36,77.471 50.05,77.471 50.246,77.275 v2(50.6,77.275) 53.125,77.275 v2(53.15,77.25)
A1: U1.F14 U201.H8 | length 20.8
  Top Layer w0.127: U1.F14@37.45,75.35 v2(37.45,75.9) ; v2(51.475,78) 51.475,77.501 51.601,77.375 51.601,73.499 U201.H8@52,73.1
  Inner-1 w0.127: v2(37.45,75.9) 37.45,76.321 39.152,78.023 51.452,78.023 v2(51.475,78)
A2: U1.E13 U201.J8 | length 22
  Top Layer w0.127: U1.E13@36.65,74.55 v2(37.041,74.941) ; U201.J8@52,73.9 v2(52,78)
  Inner-1 w0.127: v2(37.041,74.941) 37.041,76.341 39.061,78.361 51.639,78.361 v2(52,78)
A3: U1.D13 U201.J7 | length 23.6
  Top Layer w0.127: U1.D13@35.85,74.55 v2(36.25,74.95) ; U201.J7@52.8,73.9 52.789,73.911 52.789,77.989 v2(52.8,78)
  Inner-1 w0.127: v2(36.25,74.95) 36.65,75.35 36.65,76.321 38.952,78.623 52.177,78.623 v2(52.8,78)
A4: U1.E14 U201.J3 | length 25.8
  Top Layer w0.127: v2(36.2,75.9) 36.2,75.8 U1.E14@36.65,75.35 ; v2(53.875,77.25) 53.903,77.222 53.903,76.597 55.1,75.4 55.1,74.8 U201.J3@56,73.9
  Inner-1 w0.127: v2(36.2,75.9) 36.2,77.529 37.556,78.885 52.751,78.885 53.875,77.761 v2(53.875,77.25)
A5: U1.L1 U201.J2 | length 27.8
  Top Layer w0.127: U1.L1@41.45,64.95 42.8,63.6 v2(43.3,63.6) ; U201.J2@56.8,73.9 v2(57.2,73.5)
  Inner-1 w0.127: v2(43.3,63.6) 56.546,63.6 58.675,65.729 58.675,72.275 57.45,73.5 v2(57.2,73.5)
A6: R202.1 U1.N1 U201.H3 | length 27
  Top Layer w0.127: U1.N1@43.05,64.95 43.552,64.448 v2(43.552,64.003) ; v2(51.2,64) R202.1@51.2,64.65 ; U201.H3@56,73.1 v2(56.4,73.5)
  Inner-1 w0.127: v2(43.552,64.003) 43.797,64.003 43.938,63.862 50.787,63.862 50.925,64 v2(51.2,64) 51.525,64 51.663,63.862 56.408,63.862 58.413,65.867 58.413,71.998 57.35,73.061 56.839,73.061 v2(56.4,73.5)
A7: R204.1 U1.N2 U201.H2 | length 25.4
  Top Layer w0.127: U1.N2@43.05,65.75 43.45,65.35 44.1,65.35 45.225,64.225 v2(45.925,64.225) 46.419,64.225 46.819,64.625 R204.1@46.825,64.625 ; U201.H2@56.8,73.1 v2(57.2,72.7)
  Inner-1 w0.127: v2(45.925,64.225) 46.061,64.361 51.539,64.361 51.761,64.139 56.314,64.139 58.151,65.976 58.151,71.749 v2(57.2,72.7)
A8: R206.1 U1.H14 U201.H1 | length 23.6
  Top Layer w0.127: U1.H14@39.05,75.35 v2(39.05,75.9) ; R206.1@48,76.9 48.125,76.775 v2(48.625,76.775) ; v2(56.1,76.525) 56.48,76.525 58.098,74.906 58.098,73.599 U201.H1@57.6,73.1
  Inner-1 w0.127: v2(39.05,75.9) 39.45,76.3 39.85,76.3 40.235,76.685 46.878,76.685 47.123,76.439 47.739,76.439 48.075,76.775 v2(48.625,76.775) 49.625,76.775 49.875,76.525 v2(56.1,76.525)
A9: R203.1 U1.G12 U201.G3 | length 22.1
  Top Layer w0.127: U1.G12@38.25,73.75 v2(38.65,74.15) v2(41.05,74.15) ; v2(48.725,75.825) 48.925,75.625 R203.1@49.4,75.625 ; v2@54.05,75.8 54.8,75.05 54.8,73.5 U201.G3@56,72.3
  Inner-1 w0.127: v2(41.05,74.15) 41.05,74.75 41.5,75.2 41.739,75.439 48.349,75.439 48.725,75.814 v2(48.725,75.825) v2(54.05,75.825)
A10: U1.J14 U201.H9 | length 15
  Top Layer w0.127: v2(39.8,75.9) 39.8,75.4 U1.J14@39.85,75.35 ; v2(48.975,76.35) 49.598,76.35 49.9,76.048 49.9,73.745 50.545,73.1 U201.H9@51.2,73.1
  Inner-1 w0.127: v2@39.85,75.9 39.85,75.929 40.343,76.423 46.769,76.423 47.015,76.177 47.882,76.177 48.055,76.35 v2(48.975,76.35)
A11: U1.L13 U201.G2 | length 16.7
  Top Layer w0.127: U1.L13@41.45,74.55 v2(41.8,74.2) ; v2(56.4,72.7) U201.G2@56.8,72.3
  Inner-1 w0.127: v2(41.8,74.2) 42.15,74.55 43.229,74.55 43.794,73.986 47.406,73.986 48.068,73.323 55.777,73.323 v2(56.4,72.7) 56.462,72.7 v2@56.498,72.665
A12: U1.M13 U201.G1 | length 16.7
  Top Layer w0.127: U1.M13@42.2,74.55 U1.M13@42.25,74.55 v2(42.65,74.15) ; v2(57.2,71.9) U201.G1@57.6,72.3
  Inner-1 w0.127: v2(42.65,74.15) 43.259,74.15 43.685,73.724 47.297,73.724 47.96,73.061 55.439,73.061 56.2,72.3 56.8,72.3 v2(57.2,71.9)
A13: U1.N14 U201.G7 | length 12.6
  Top Layer w0.127: U1.N14@43.05,75.35 43.463,75.764 44.236,75.764 v2(45,75) ; v2(52.402,74.899) 52.402,72.699 U201.G7@52.8,72.3
  Inner-1 w0.127: v2(45,75) 52.062,75 52.126,74.936 52.364,74.936 v2(52.402,74.899)
A14: U1.F12 U201.G8 | length 17.6
  Top Layer w0.127: U1.F12@37.45,73.75 v2(37.85,74.15) ; v2(48.2,75.8) 48.2,75.075 50.574,72.7 51.6,72.7 U201.G8@52,72.3
  Inner-1 w0.127: v2(37.85,74.15) 38.5,74.8 40.229,74.8 41.59,76.161 46.661,76.161 47.022,75.8 v2(48.2,75.8)
AGND: C314.1 C338.1 C711.2 C718.2 C719.2 C728.1 D700.2 L702.1 R703.2 X700.1 | length 16.5
  Top Layer w0.203: L702.1@7.104,16.524 L702.1@7.504,16.524 10.564,16.524 X700.1@10.72,16.68
  Bottom Layer w0.305: X700.1@10.72,16.68 12.38,16.68 14.146,18.446 D700.2@14.376,18.446 ; v1(23.8,10.6) 23.8,12.121 23.979,12.3 C338.1@26.552,12.3
  Bottom Layer w0.508: C728.1@15.1,15.3 v1(15.9,15.3) R703.2@16.7,15.3 C711.2@16.7,16.2 ; v1(18.9,15.3) C719.2@19.7,15.3 ; C718.2@21.2,17.4 v1(22,17.4)
  other v1: 6.7,10.6 10.8,10.6 19.7,10.6 26.3,10.6 15.9,11.3 12.3,13.2 26.4,14.8 15.2,17.7
CAS: U1.M14 U201.F7 | length 12.1
  Top Layer w0.127: U1.M14@42.25,75.35 42.65,74.95 44.244,74.95 v2(44.247,74.947) ; v2@47.25,74.589 47.286,74.625 47.908,74.625 50.635,71.899 52.402,71.899 U201.F7@52.8,71.5
  Inner-1 w0.127: v2(44.247,74.947) 44.57,74.624 47.174,74.624 v2(47.175,74.625)
CKE: U1.F11 U201.F3 | length 21.1
  Top Layer w0.127: U1.F11@37.45,72.95 v2(37.85,73.35) ; v2@43.41,73.36 v2@43.425,73.375 ; v2@43.45,73.35 44.451,73.35 44.825,73.724 46.381,73.724 46.8,73.305 v2(46.8,73.3) ; v2(54.8,72.7) U201.F3@56,71.5 55.6,71.9
  Inner-1 w0.127: v2(37.85,73.35) 38.2,73.7 39.3,73.7 40.1,72.9 40.6,72.9 41.05,73.35 41.1,73.4 v2(43.45,73.4) ; v2(46.8,73.3) 47.35,73.3 47.851,72.799 54.701,72.799 v2(54.8,72.7)
CLASS0: R432.2 U1.A13 U403.4 | length 36.1
  Top Layer w0.127: R432.2@27.5,45.3 v1(27.5,44.6) 27.5,44.4 28.265,43.635 U403.4@28.265,43.3 ; v1@32.45,74.3 32.7,74.55 U1.A13@33.45,74.55
  Bottom Layer w0.127: v1(27.5,44.6) 27.5,45.2 27.1,45.6 27.1,49.371 26.301,50.169 26.301,59.801 28.1,61.6 28.1,63.3 30.038,65.238 30.038,69.838 32.4,72.2 v1(32.4,74.3)
CLASS1: R431.2 U1.B11 U402.4 | length 38.1
  Top Layer w0.127: U402.4@24.965,43.3 25.3,43.635 25.3,44.2 v1(25.7,44.6) R431.2@25.7,45.3 ; v1@30.05,72.4 30.45,72.4 30.6,72.25 32.25,72.25 32.8,72.8 32.8,73.05 33.1,73.35 33.85,73.35 U1.B11@34.25,72.95
  Bottom Layer w0.127: v1(25.7,44.6) 25.7,45.2 26.8,46.3 26.8,49.3 26.039,50.061 26.039,59.964 27.838,61.762 27.838,63.45 29.776,65.388 29.776,69.971 30.6,70.795 30.6,71.9 30.1,72.4 v1@30,72.4
  other v1: 30.05,72.45
CONFIG_1: R209.2 R211.1 U1.C12 | length 10.4
  Top Layer w0.127: R209.2@32.8,77.7 33.4,78.3 v2(35.1,78.3) 35.119,78.281 37.819,78.281 R211.1@38,78.1 ; v2(34.65,74.15) U1.C12@35.05,73.75
  Inner-1 w0.127: v2(34.65,74.15) 35.1,74.6 v2(35.1,78.3)
D0: R205.8 U1.N4 | length 6.1
  Top Layer w0.127: U1.N4@43.05,67.35 v2(43.45,66.95) ; v2(47.85,67.275) 47.875,67.25 48.325,67.25 R205.8@48.4,67.175
  Inner-1 w0.127: v2(43.45,66.95) 43.475,66.925 45.075,66.925 45.5,66.5 46.289,66.5 47.064,67.275 v2(47.85,67.275)
D1: R205.7 U1.M5 | length 6.7
  Top Layer w0.127: U1.M5@42.25,68.15 v2(42.65,68.55) ; v2(47.85,67.825) 47.9,67.775 48.35,67.775 R205.7@48.4,67.725
  Inner-1 w0.127: v2(42.65,68.55) 43.375,67.825 v2(47.85,67.825)
D2: R205.6 U1.N5 | length 5.7
  Top Layer w0.127: U1.N5@43.05,68.15 43.425,68.525 v2(43.425,68.55) ; v2@47.577,68.227 47.575,68.225 R205.6@48.4,68.225
  Inner-1 w0.127: v2(43.425,68.55) 43.747,68.228 v2(47.577,68.228)
D3: R205.5 U1.N6 | length 5.7
  Top Layer w0.127: U1.N6@43.05,68.95 43.4,69.3 v2(43.425,69.3) ; v2(47.85,69) 48.075,68.775 R205.5@48.4,68.775
  Inner-1 w0.127: v2(43.425,69.3) 45.4,69.3 45.7,69 v2(47.85,69)
D4: R207.8 U1.P8 | length 5
  Top Layer w0.127: U1.P8@43.85,70.55 44.25,70.15 v2(45.4,70.15) ; v2(47.85,69.725) 48.075,69.5 R207.8@48.4,69.5
  Inner-1 w0.127: v2(45.4,70.15) 45.825,69.725 v2(47.85,69.725)
D5: R207.7 U1.P7 | length 4.7
  Top Layer w0.127: U1.P7@43.85,69.75 45.65,69.75 v2(46,70.1) ; v2(47.552,70.103) 48.347,70.103 48.35,70.1 R207.7@48.4,70.05
  Inner-1 w0.127: v2(46,70.1) 46.003,70.103 v2(47.552,70.103)
D6: R207.6 U1.L8 | length 7.3
  Top Layer w0.127: U1.L8@41.45,70.55 v2(41.8,70.2) ; v2(47.85,70.525) R207.6@48.375,70.525 ; R207.6@48.387,70.525 R207.6@48.375,70.525 ; R207.6@48.4,70.55 R207.6@48.375,70.525
  Inner-1 w0.127: v2(41.8,70.2) 42.85,70.2 43.175,70.525 v2(47.85,70.525)
D7: R207.5 U1.K7 | length 8.4
  Top Layer w0.127: U1.K7@40.65,69.75 v2(41.05,70.15) ; v2(47.552,70.903) 47.552,70.877 47.55,70.875 47.775,71.1 R207.5@48.4,71.1
  Inner-1 w0.127: v2(41.05,70.15) 41.461,70.561 42.772,70.561 43.114,70.903 v2(47.552,70.903)
D8: R212.8 U1.N7 | length 16.7
  Top Layer w0.127: U1.N7@43.05,69.75 43.025,69.75 v2(43.425,70.15) ; v2(56.25,64.625) 56.556,64.319 56.981,64.319 R212.8@57.05,64.25
  Inner-1 w0.127: v2(43.425,70.15) 43.975,69.6 45.579,69.6 45.815,69.364 49.484,69.364 53.033,65.815 55.024,65.815 56.214,64.625 v2(56.25,64.625)
D9: R212.7 U1.N8 | length 17.8
  Top Layer w0.127: v2(42.65,70.95) U1.N8@43.05,70.55 ; v2(56.264,65.085) 56.301,65.085 56.586,64.8 R212.7@57.05,64.8
  Inner-1 w0.127: v2(42.65,70.95) 42.964,71.264 47.954,71.264 53.142,66.077 55.272,66.077 v2(56.264,65.085)
D10: R212.6 U1.M11 | length 18.1
  Top Layer w0.127: U1.M11@42.25,72.95 v2(42.6,72.6) ; v2(56.428,65.553) 56.447,65.553 56.7,65.3 R212.6@57.05,65.3
  Inner-1 w0.127: v2(42.6,72.6) 43,72.2 43.8,72.2 43.988,72.388 45.587,72.388 46.438,71.537 48.052,71.537 53.25,66.339 55.642,66.339 v2(56.428,65.553)
D11: R213.5 U1.N11 | length 13.9
  Top Layer w0.127: U1.N11@43.05,72.95 v2(43.4,72.6) ; v2(53.4,66.7) 53.4,65.9 R213.5@53.45,65.85
  Inner-1 w0.127: v2(43.4,72.6) 43.45,72.65 45.696,72.65 46.547,71.799 48.301,71.799 v2(53.4,66.7)
D12: R212.5 U1.L2 | length 17.2
  Top Layer w0.127: U1.L2@41.45,65.75 41.85,65.35 v2(42.65,65.35) ; v2(55.75,64.5) 55.75,65.386 56.278,65.914 56.986,65.914 R212.5@57.05,65.85
  Inner-1 w0.127: v2(42.65,65.35) 42.7,65.35 43.137,64.913 55.337,64.913 v2(55.75,64.5)
D13: R213.8 U1.M1 | length 11.6
  Top Layer w0.127: U1.M1@42.25,64.95 42.25,64.938 42.65,64.537 v2(42.65,64.525) ; v2(52.2,64.5) 52.45,64.25 R213.8@53.45,64.25
  Inner-1 w0.127: v2(42.65,64.525) 45.714,64.525 45.812,64.623 51.748,64.623 51.847,64.524 52.176,64.524 v2(52.2,64.5)
D14: R213.7 U1.M3 | length 12.2
  Top Layer w0.127: U1.M3@42.25,66.55 v2(42.65,66.15) ; v2(52.2,65.5) 52.9,64.8 R213.7@53.45,64.8
  Inner-1 w0.127: v2(42.65,66.15) 43.45,65.35 44.375,65.35 44.55,65.175 46.55,65.175 46.875,65.5 v2(52.2,65.5)
D15: R213.6 U1.P6 | length 11.1
  Top Layer w0.127: U1.P6@43.85,68.95 44.1,68.7 v2(44.6,68.7) ; v2(52.2,66.05) 52.95,65.3 R213.6@53.45,65.3
  Inner-1 w0.127: v2@44.6,68.726 44.708,68.617 48.008,68.617 50.575,66.05 v2(52.2,66.05)
DAC_BL: C5.2 R26.1 TP12.1 X500.15 | length 18.6
  Top Layer w0.152: R26.1@42.6,55.7 42.525,55.625 42.525,53.825 44,52.35 44,52.2 44,50.3 45,49.3 52,49.3 v1(52.6,49.9) ; v1@52.65,50.15 X500.15@52.65,51.2
  Bottom Layer w0.152: v1(52.6,49.9) TP12.1@52.6,51
  Bottom Layer w0.508: v1(52.6,49.9) 52.625,49.9 52.688,49.964 53.721,49.964 C5.2@53.75,49.993
DAC_NMUTE: R721.1 R723.1 TP702.1 U1.H11 | length 52.9
  Top Layer w0.127: v2(38.7,73.3) U1.H11@39.05,72.95
  Inner-1 w0.127: v1(30.7,73.35) 30.703,73.347 33.047,73.347 33.45,73.75 36.65,73.75 37.45,72.95 38.35,72.95 v2(38.7,73.3)
  Bottom Layer w0.152: TP702.1@14.8,42.8 15,42.6 16,43.6 22.587,43.6 ; R723.1@22.587,44.4 22.587,43.6 ; R721.1@22.6,42.7 22.587,42.713 22.587,43.6 ; R723.1@22.6,44.4 23.7,44.4 26.2,46.9 26.2,49.1 25.477,49.823 25.477,60.25 26.511,61.284 26.511,62.523 29.501,65.513 29.501,72.624 30.177,73.3 v1@30.7,73.3
DBG_EN: R4.1 U1.K4 | length 9.1
  Top Layer w0.127: U1.K4@40.65,67.35 v2(41.05,66.95) ; v1(45.125,61.925) 45.55,61.925 R4.1@45.9,62.275
  Inner-1 w0.127: v2(41.05,66.95) 41.4,66.6 41.4,64.129 43.604,61.925 v1(45.125,61.925)
DQM0: U1.F13 U201.E8 | length 26.1
  Top Layer w0.127: U1.F13@37.45,74.55 v2(37.841,74.941) ; U201.E8@52,70.7 52.399,71.099 52.962,71.099 53.511,71.647 53.511,77.614 v2(53.5,77.625)
  Inner-1 w0.127: v2(37.841,74.941) 37.841,76.341 39.261,77.761 50.6,77.761 50.736,77.625 v2(53.5,77.625)
DQM1: U1.G13 U201.F1 | length 26.7
  Top Layer w0.127: U1.G13@38.25,74.55 38.648,74.949 38.648,76.248 v2(39,76.6) ; v2@56.375,76.9 56.476,76.9 58.361,75.015 58.361,72.261 U201.F1@57.6,71.5
  Inner-1 w0.127: v2(39,76.6) 39.609,77.209 49.941,77.209 50.261,76.889 56.389,76.889 v2(56.4,76.9)
EARTH: C314.2 C331.2 C337.2 C338.2 C709.2 X300.9 X301.9 | length 61.9
  Bottom Layer w0.305: C338.2@29.448,12.3 29.488,12.34 29.64,12.34 C338.2@29.6,12.3 ; X300.9@36.1,12.3 36.06,12.34 X300.9@36.105,12.34
  Bottom Layer w0.635: X300.9@36.105,12.34 36.105,7.4 60.1,7.4 ; X301.9@60.1,12.335 60.1,7.4 ; 79.2,7.4 60.1,7.4
  Bottom Layer w1.016: C331.2@54.567,13.551 54.6,12.335 C331.2@54.6,13.552 ; 79.2,7.5 C337.2@79.2,13.6
  other v1: 0.9,0.8 6.7,0.8 12.5,0.8 18.9,0.8 25.2,0.8 32.9,0.9 41.5,0.9 47.8,0.9 53.1,0.9 59,0.9 64.6,0.9 69.6,0.9 75.2,0.9 84,0.9 0.9,4 45,4.75 34.6,5.9 70,6.9 76.1,6.9 84,6.9 61,7 0.9,7.2 10.5,7.2 16.9,7.2 21.9,7.2 26.7,7.2 41.5,7.5 49.75,7.5 55,7.5 29.7,8.6 39,9.75 66.3,10.2 84,11.8 52.5,12.5 57.5,13 75.5,13 29.7,15.9 84,16.7 81.4,20.2 83.95,23.55
EMC_CLK: C206.2 R214.1 U201.F2 | length 15.4
  Top Layer w0.127: R214.1@45.575,68.875 46.425,68.875 46.375,68.925 v2(46.375,72.525) ; v2(56.4,71.9) U201.F2@56.8,71.5
  Inner-1 w0.127: v2(46.375,72.525) 46.386,72.536 52.164,72.536 52.4,72.3 55.7,72.3 56.1,71.9 v2(56.4,71.9)
ETH_CRS_DV: R304.1 U1.L5 | length 25.7
  Top Layer w0.127: U1.L5@41.45,68.15 v2(41.85,67.75) ; v1(58.9,55.4) R304.1@59.7,55.4
  Inner-1 w0.127: v2(41.85,67.75) 41.988,67.612 41.988,63.912 43.4,62.5 48.4,62.5 v1(48.675,62.225)
  Bottom Layer w0.127: v1(48.675,62.225) 49.08,62.225 51.268,60.037 52.562,60.037 56.897,55.701 58.599,55.701 v1(58.9,55.4)
ETH_MDC: R337.2 U1.D5 U333.33 | length 37.2
  Top Layer w0.127: U1.D5@35.85,68.15 36.25,67.75 36.25,63.15 v1(37,62.4) ; v1(57.2,51.1) 58.9,51.1 R337.2@59.5,50.5 R337.2@59.55,50.45 ; R337.2@59.5,50.45 R337.2@59.55,50.45 ; U333.33@61.7,50.45 R337.2@59.55,50.45
  Bottom Layer w0.127: v1(37,62.4) 38.595,62.4 43.12,57.875 52.63,57.875 57.2,53.305 v1(57.2,51.1)
ETH_MDIO: R334.1 U1.L6 U333.34 | length 35.6
  Top Layer w0.127: U1.L6@41.45,68.95 v2(41.85,68.55) ; R334.1@59.5,49.7 v1(60.7,49.7) 60.95,49.95 U333.34@61.7,49.95
  Inner-1 w0.127: v2(41.85,68.55) 42.25,68.15 42.25,64.139 43.314,63.075 v1(43.925,63.075)
  Bottom Layer w0.127: v1(43.925,63.075) 43.402,62.552 43.402,58.894 43.896,58.399 52.931,58.399 59.3,52.029 59.3,51.1 v1(60.7,49.7)
ETH_REFCLK: R336.1 U1.L10 U1.N9 | length 5.9
  Top Layer w0.127: U1.L10@41.45,72.15 41.851,71.749 42.651,71.749 U1.N9@43.05,71.35 43.448,70.952 44.477,70.952 v1(45.35,71.825)
  Bottom Layer w0.127: R336.1@45.29,70.675 45.35,70.735 v1(45.35,71.825)
ETH_REFCLK2: R327.1 R336.2 U333.23 | length 30.3
  Top Layer w0.152: R327.1@57.2,57 v1(57.2,56.2) 57.6,56.2 58.3,55.5 58.3,55.2 58.9,54.6 59.3,54.6 64.128,54.6 64.725,54.004 64.725,53.727 64.95,53.501 U333.23@64.95,53.2
  Bottom Layer w0.152: R336.2@46.29,70.675 47.3,69.665 47.3,64.394 51.382,60.311 53.089,60.311 v1(57.2,56.2)
ETH_RXD0: R303.1 R331.1 U1.P11 | length 28.3
  Top Layer w0.127: U1.P11@43.85,72.95 44.074,72.726 45.726,72.726 v1(46.2,73.2)
  Top Layer w0.152: v1(58.9,56.2) R303.1@59.7,56.2
  Bottom Layer w0.152: v1(46.2,73.2) 46.2,71.8 47.6,70.4 47.6,64.5 51.5,60.6 54.1,60.6 58.5,56.2 v1(58.9,56.2) R331.1@59.7,56.2
ETH_RXD1: R302.1 R328.1 U1.K3 | length 25.3
  Top Layer w0.127: U1.K3@40.65,66.55 v2(41,66.2) ; R328.1@58.1,57 v1(58.9,57) R302.1@59.7,57
  Inner-1 w0.152: v2(41,66.2) 41,64.05 43.65,61.4 45.525,61.4 45.775,61.65 51.85,61.65 52.2,61.3 v1(52.2,61.2)
  Bottom Layer w0.152: v1(52.2,61.2) 52.5,60.9 54.206,60.9 58.106,57 v1(58.9,57)
ETH_TXD0: R200.2 U333.25 | length 19.8
  Top Layer w0.127: R200.2@48.25,61.1 48.325,61.175 v2(48.925,61.175) ; v2(58.1,53.4) 59.729,53.4 60.39,54.061 62.232,54.061 63.54,54.06 63.95,53.65 U333.25@63.95,53.2
  Inner-1 w0.127: v2(48.925,61.175) 49.496,61.175 57.271,53.4 v2(58.1,53.4)
ETH_TXD1: R201.2 U333.26 | length 19.3
  Top Layer w0.127: R201.2@48.25,60.275 48.375,60.4 48.675,60.4 v2(48.925,60.65) ; v2(57.8,53) 57.802,53.002 59.702,53.002 60.498,53.799 62.123,53.799 63.127,53.798 63.45,53.475 U333.26@63.45,53.2
  Inner-1 w0.127: v2(48.925,60.65) 49.65,60.65 57.3,53 v2(57.8,53)
ETH_TXEN: R338.2 U1.K2 U333.24 | length 32
  Top Layer w0.127: U1.K2@40.65,65.75 41.05,65.35 41.05,64.786 42.9,62.936 42.9,60.9 v1(44.9,58.9) ; R338.2@58.6,54 v1(59.5,54) 59.6,54 59.922,54.322 63.828,54.322 64.45,53.7 U333.24@64.45,53.2
  Bottom Layer w0.127: v1(44.9,58.9) 52.8,58.9 57.7,54 v1(59.5,54)
ETHIN_T1_N: T300.22 X300.2 | length 33.9
  Top Layer w0.22: X300.2@39.52,16.15 39.52,13.1 42.22,10.4 48.6,10.4 49,10.8 49,12.927 51.773,15.7 57.226,15.7 59.753,18.227 59.753,20.947 59.045,21.655 T300.22@59.045,22.96
ETHIN_T1_P: T300.23 X300.1 | length 33.6
  Top Layer w0.22: X300.1@38.25,13.61 38.25,13.55 41.947,9.853 48.827,9.853 49.547,10.573 49.547,12.7 49.973,13.126 50.012,13.165 50.154,13.165 50.323,13.335 50.323,13.476 50.323,13.618 50.493,13.788 50.635,13.788 50.776,13.788 50.946,13.957 50.946,14.099 50.946,14.24 51.115,14.41 51.257,14.41 51.398,14.41 51.568,14.58 51.568,14.721 51.724,14.877 52,15.153 57.453,15.153 60.3,18 60.3,22.1 60.315,22.115 T300.23@60.315,22.96
ETHIN_T2_N: T300.19 X300.6 | length 21.5
  Top Layer w0.22: X300.6@44.5,16.1 45.448,15.152 48.378,15.152 50.626,17.4 51.4,17.4 51.461,17.4 51.506,17.355 51.638,17.223 51.814,17.223 51.946,17.355 51.946,17.4 51.946,17.768 52.078,17.9 52.254,17.9 52.386,17.768 52.386,17.4 52.386,17.355 52.518,17.223 52.694,17.223 52.826,17.355 52.826,17.4 52.826,17.768 52.958,17.9 53.134,17.9 53.266,17.768 53.266,17.532 53.398,17.4 53.706,17.4 53.926,17.4 53.978,17.451 54.257,17.731 54.321,17.731 54.507,17.731 54.632,17.855 54.632,18.042 54.6,18.074 54.34,18.334 54.34,18.52 54.464,18.645 54.651,18.645 54.911,18.385 54.943,18.353 55.13,18.353 55.254,18.477 55.254,18.664 55.222,18.696 54.962,18.956 54.962,19.143 55.086,19.267 55.273,19.267 55.44,19.1 55.627,19.1 55.844,19.318 56,19.474 56,19.88 56,20.1 56,20.9 55.235,21.665 T300.19@55.235,22.96
ETHIN_T2_P: T300.20 X300.3 | length 21.8
  Top Layer w0.22: X300.3@40.8,13.6 41.805,14.605 48.605,14.605 50.853,16.853 54.153,16.853 56.547,19.247 56.547,22.422 56.505,22.464 T300.20@56.505,22.96
ETHOUT_T1_N: T301.22 X301.2 | length 24.8
  Top Layer w0.22: v1(77.5,18.4) 77.2,18.4 76.953,18.647 76.953,19.827 77.673,20.547 78.412,20.547 78.895,21.03 T301.22@78.895,22.96
  Bottom Layer w0.22: 63.173,17.373 62.427,16.627 62.427,15.673 62.7,15.4 63,15.4 63.52,15.92 X301.2@63.52,16.15 ; 63.2,17.373 75.273,17.373 76.553,18.653 77.247,18.653 v1(77.5,18.4)
ETHOUT_T1_P: T301.23 X301.1 | length 25.3
  Top Layer w0.22: v1(77.5,19.2) 77.5,19.6 77.9,20 78.638,20 80.165,21.527 T301.23@80.165,22.96
  Bottom Layer w0.22: X301.1@62.3,13.6 62.3,15.026 61.88,15.446 61.88,16.854 62.946,17.92 ; 63,17.92 75.02,17.92 76.3,19.2 v1(77.5,19.2)
ETHOUT_T2_N: T301.19 X301.6 | length 19.8
  Top Layer w0.22: X301.6@68.6,16.1 68.6,13.2 69.4,12.4 70.1,12.4 73.15,15.45 73.284,15.584 73.284,15.771 73.188,15.867 73.188,16.054 73.313,16.178 73.499,16.178 73.689,15.989 73.721,15.957 73.907,15.957 74.032,16.081 74.032,16.268 74,16.3 73.81,16.489 73.81,16.676 73.935,16.801 74.122,16.801 74.311,16.611 74.343,16.579 74.53,16.579 74.654,16.704 74.654,16.89 74.622,16.922 74.433,17.112 74.433,17.298 74.557,17.423 74.744,17.423 74.84,17.327 75.027,17.327 75.244,17.544 75.4,17.7 75.4,18.08 75.4,18.3 75.4,20.374 75.4,21.1 75.085,21.415 T301.19@75.085,22.96
ETHOUT_T2_P: T301.20 X301.3 | length 19.9
  Top Layer w0.22: X301.3@64.79,13.61 65.9,12.5 68.526,12.5 69.173,11.853 70.327,11.853 75.947,17.473 75.947,20.147 75.947,21.127 76.355,21.535 T301.20@76.355,22.96
FL_MISO: U1.B12 U202.2 | length 18.2
  Top Layer w0.127: v2(31.7,73.95) 31.9,73.75 32.85,73.75 33.25,74.15 33.85,74.15 U1.B12@34.25,73.75
  Top Layer w0.152: v1(25.2,65.4) 25.2,64.233 U202.2@25.215,64.218
  Inner-1 w0.152: v1@26,72.9 27.05,73.95 v2(31.7,73.95)
  Bottom Layer w0.152: v1(25.2,65.4) 25.2,72.1 26,72.9 v1(26,72.95)
FL_MOSI: U1.C10 U202.5 | length 8
  Top Layer w0.127: U202.5@27.65,71.55 28,71.9 31.6,71.9 31.65,71.95 32.65,71.95 33.25,72.55 34.65,72.55 U1.C10@35.05,72.15
FL_SCK: U1.B13 U202.6 | length 10
  Top Layer w0.127: U202.6@26.5,71.4 26.5,72.4 28,73.9 30.9,73.9 31.95,74.95 33.85,74.95 U1.B13@34.25,74.55
FL_SIO2: U1.C11 U202.3 | length 17.2
  Top Layer w0.127: v2(34.7,73.3) U1.C11@35.05,72.95
  Top Layer w0.152: U202.3@26.485,64.168 26.485,64.785 26.7,65 v1(26.7,65.5) ; v1(28.2,73) 30.3,73 30.6,72.7 v2(31.05,72.7)
  Inner-1 w0.152: v2(31.05,72.7) 31.55,72.2 32.8,72.2 33.9,73.3 v2(34.7,73.3)
  Bottom Layer w0.152: v1@26.7,65.6 26.7,71.5 v1(28.2,73)
FL_SIO3: U1.C14 U202.7 | length 12.8
  Top Layer w0.127: U202.7@25.2,71.4 25.2,73 26.4,74.2 30.8,74.2 32.4,75.8 34.6,75.8 U1.C14@35.05,75.35
FL_SSEL: U1.C9 U202.1 | length 15.4
  Top Layer w0.152: U202.1@23.945,64.168 23.945,64.645 24,64.7 24,65.7 29.85,71.55 32.3,71.55 v2(32.308,71.558) ; v2(34.65,71.75) U1.C9@35.05,71.35
  Inner-1 w0.152: v2(32.308,71.558) 32.65,71.9 33.2,71.9 33.35,71.75 v2(34.65,71.75)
